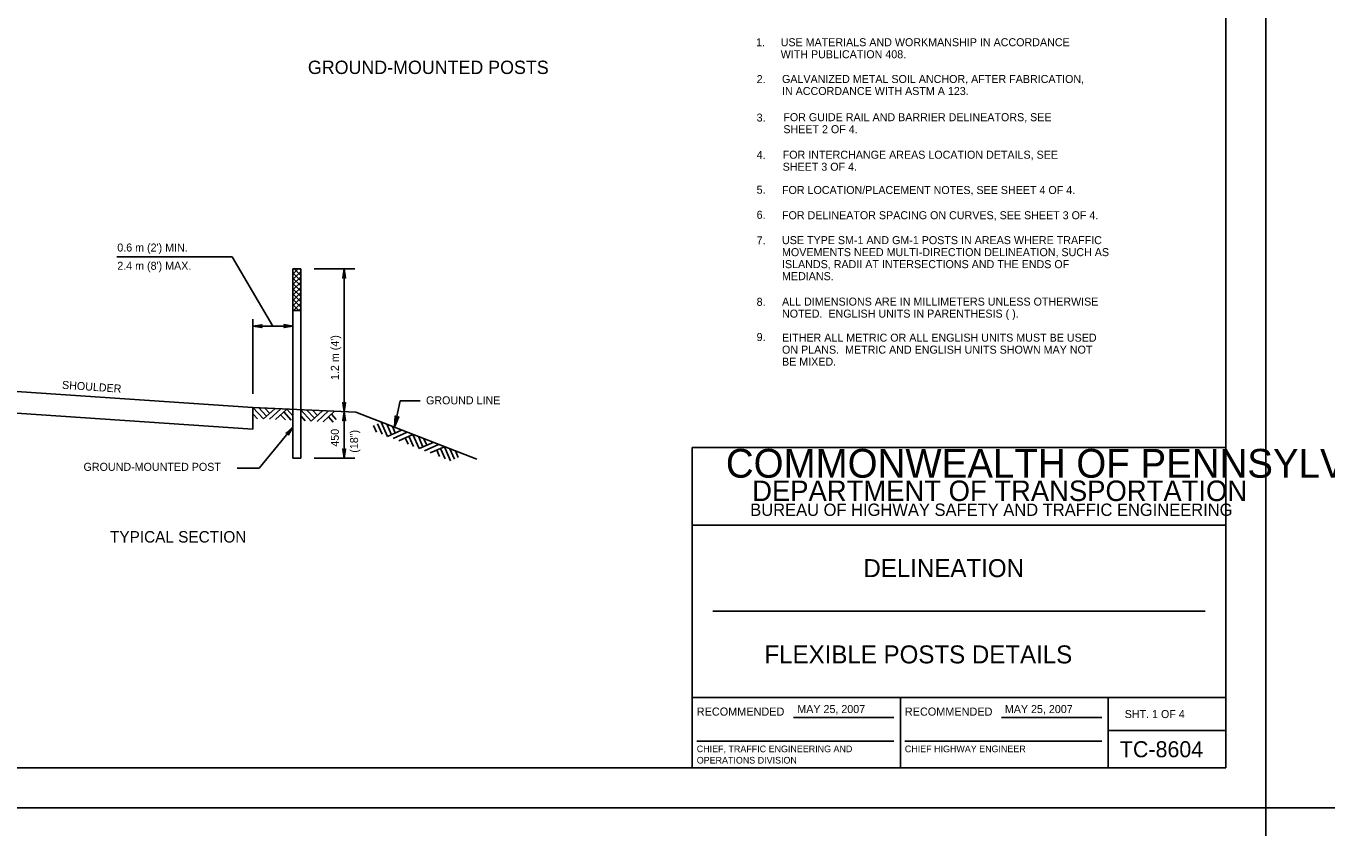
# Model space of a CAD drawing. Extents: x 640253 to 641999, y 298458 to 299646.
# Drawn here: x 640629.6 to 641116.9, y 299044.1 to 299344.6 of the extents above; entities that cross this region are included whole.
import ezdxf

# ---------------------------------------------------------------- set-up
doc = ezdxf.new("R2010")
doc.units = 0
for name, color, linetype in [('1', 7, 'Continuous'), ('2', 7, 'Continuous'), ('PLT-BNDY', 7, 'Continuous')]:
    doc.layers.add(name, color=color, linetype=linetype)

msp = doc.modelspace()

# ---------------------------------------------------------------- linework, layer by layer
at = {"layer": '1'}
for p, q in [((641079.31, 299066.63), (641079.31, 299630.63)), ((640879.31, 299066.63), (640879.31, 299186.63)), ((640879.31, 299186.63), (641079.31, 299186.63)), ((641079.31, 299157.63), (640879.31, 299157.63)), ((640887.06, 299125.31), (641071.56, 299125.31)), ((640879.31, 299093), (641079.31, 299093)), ((640957.31, 299093), (640957.31, 299066.63)), ((641035.19, 299066.63), (641035.19, 299093)), ((640917.24, 299085.57), (640954.87, 299085.57)), ((640995.24, 299085.57), (641032.87, 299085.57)), ((641035.19, 299080.63), (641079.31, 299080.63)), ((640880.99, 299076.68), (640954.87, 299076.68)), ((640958.99, 299076.68), (641032.87, 299076.68)), ((641079.31, 299066.63), (640293.31, 299066.63)), ((640293.31, 299066.63), (640879.31, 299066.63))]:
    msp.add_line(p, q, dxfattribs=at)
at = {"layer": '2'}
for p, q in [((640663.62, 299258.11), (640706.89, 299258.11)), ((640722.13, 299232.16), (640706.89, 299258.11)), ((640729.61, 299253.58), (640732.55, 299253.58)), ((640729.61, 299237.99), (640729.61, 299253.58)), ((640729.61, 299251.64), (640731.55, 299253.58)), ((640729.61, 299249.66), (640732.55, 299252.6)), ((640732.55, 299249.16), (640729.61, 299252.1)), ((640729.61, 299247.68), (640732.55, 299250.62)), ((640732.55, 299251.14), (640730.12, 299253.58)), ((640732.55, 299253.12), (640732.1, 299253.58)), ((640732.55, 299237.99), (640732.55, 299253.58)), ((640737.54, 299253.58), (640752.77, 299253.58)), ((640748.8, 299253.58), (640748.8, 299200.09)), ((640732.55, 299247.18), (640729.61, 299250.12)), ((640729.61, 299245.7), (640732.55, 299248.64)), ((640732.55, 299245.2), (640729.61, 299248.14)), ((640729.61, 299243.72), (640732.55, 299246.66)), ((640732.55, 299243.22), (640729.61, 299246.16)), ((640729.61, 299241.74), (640732.55, 299244.68)), ((640732.55, 299241.24), (640729.61, 299244.18)), ((640729.61, 299239.76), (640732.55, 299242.7)), ((640732.55, 299239.26), (640729.61, 299242.2)), ((640729.83, 299237.99), (640732.55, 299240.72)), ((640731.85, 299237.99), (640729.61, 299240.22)), ((640729.86, 299237.99), (640729.61, 299238.25)), ((640729.61, 299237.99), (640732.55, 299237.99)), ((640729.61, 299182.73), (640729.61, 299237.99)), ((640731.81, 299237.99), (640732.55, 299238.74)), ((640732.55, 299182.73), (640732.55, 299237.99)), ((640714.64, 299234.74), (640714.64, 299206.78)), ((640714.64, 299232.16), (640729.61, 299232.16)), ((640605.44, 299208.99), (640714.64, 299201.64)), ((640767.69, 299194.24), (640769.87, 299204.1)), ((640769.87, 299204.1), (640777.37, 299204.1)), ((640605.44, 299200.94), (640714.64, 299193.59)), ((640714.64, 299193.59), (640714.64, 299201.64)), ((640714.64, 299201.64), (640753.14, 299199.89)), ((640714.64, 299201.64), (640718.57, 299197.35)), ((640714.64, 299199.31), (640716.34, 299197.45)), ((640716.86, 299201.54), (640719.72, 299198.41)), ((640722.8, 299201.21), (640718.56, 299197.35)), ((640719.08, 299201.44), (640720.88, 299199.48)), ((640725.09, 299201.16), (640720.79, 299197.25)), ((640727.32, 299201.06), (640723.02, 299197.15)), ((640724.99, 299198.93), (640726.78, 299196.98)), ((640726.15, 299200), (640729.01, 299196.88)), ((640727.32, 299201.06), (640729.61, 299198.55)), ((640732.55, 299200.83), (640736.48, 299196.54)), ((640732.55, 299198.49), (640734.25, 299196.63)), ((640734.78, 299200.72), (640737.64, 299197.6)), ((640740.71, 299200.4), (640736.47, 299196.54)), ((640737, 299200.63), (640738.8, 299198.66)), ((640743, 299200.35), (640738.71, 299196.43)), ((640745.23, 299200.25), (640740.93, 299196.33)), ((640742.91, 299198.12), (640744.7, 299196.16)), ((640744.07, 299199.18), (640745.88, 299197.2)), ((640748.8, 299182.73), (640748.8, 299200.09)), ((640753.14, 299199.89), (640798.56, 299182.25)), ((640717.02, 299178.97), (640729.61, 299194.34)), ((640759.85, 299194.88), (640760.93, 299192.46)), ((640761.3, 299195.52), (640763.01, 299191.65)), ((640762.74, 299196.16), (640765.09, 299190.85)), ((640764.81, 299195.36), (640766.52, 299191.48)), ((640770.33, 299193.15), (640765.08, 299190.85)), ((640766.88, 299194.56), (640767.96, 299192.12)), ((640772.48, 299192.38), (640767.16, 299190.04)), ((640774.57, 299191.57), (640769.25, 299189.23)), ((640771.68, 299190.29), (640772.75, 299187.87)), ((640773.12, 299190.93), (640774.83, 299187.06)), ((640774.57, 299191.57), (640776.91, 299186.25)), ((640776.64, 299190.76), (640778.35, 299186.89)), ((640782.23, 299188.59), (640776.91, 299186.26)), ((640778.71, 299189.96), (640779.79, 299187.53)), ((640784.23, 299187.75), (640778.99, 299185.44)), ((640729.61, 299182.73), (640732.55, 299182.73)), ((640737.54, 299182.73), (640752.77, 299182.73)), ((640786.39, 299186.98), (640781.07, 299184.64)), ((640783.51, 299185.7), (640784.57, 299183.28)), ((640784.95, 299186.34), (640786.66, 299182.47)), ((640786.39, 299186.98), (640788.74, 299181.66)), ((640788.46, 299186.17), (640790.18, 299182.3)), ((640790.54, 299185.37), (640791.61, 299182.93)), ((640708.68, 299178.97), (640717.02, 299178.97))]:
    msp.add_line(p, q, dxfattribs=at)
for points in [[(640748.4, 299250.38), (640748.63, 299250.5), (640748.8, 299253.58), (640748.4, 299250.38), (640748.26, 299250.22), (640748.8, 299253.58), (640748.95, 299250.5), (640749.18, 299250.39), (640748.8, 299253.58), (640749.34, 299250.22), (640749.18, 299250.39)], [(640717.83, 299231.76), (640717.72, 299231.99), (640714.64, 299232.16), (640717.83, 299231.76), (640718, 299231.62), (640714.64, 299232.16), (640717.71, 299232.31), (640717.83, 299232.54), (640714.64, 299232.16), (640718, 299232.69), (640717.83, 299232.54)], [(640726.42, 299232.56), (640726.53, 299232.33), (640729.61, 299232.16), (640726.42, 299232.56), (640726.25, 299232.7), (640729.61, 299232.16), (640726.54, 299232.01), (640726.43, 299231.78), (640729.61, 299232.16), (640726.25, 299231.62), (640726.43, 299231.78)], [(640749.2, 299203.28), (640748.97, 299203.17), (640748.8, 299200.09), (640749.2, 299203.28), (640749.34, 299203.45), (640748.8, 299200.09), (640748.65, 299203.16), (640748.42, 299203.28), (640748.8, 299200.09), (640748.27, 299203.45), (640748.42, 299203.28)], [(640748.4, 299196.89), (640748.63, 299197.01), (640748.8, 299200.09), (640748.4, 299196.89), (640748.26, 299196.73), (640748.8, 299200.09), (640748.95, 299197.01), (640749.18, 299196.9), (640748.8, 299200.09), (640749.34, 299196.73), (640749.18, 299196.9)], [(640769.04, 299198.03), (640768.73, 299197.95), (640767.69, 299194.24), (640769.04, 299198.03), (640769.26, 299198.2), (640767.69, 299194.24), (640768.33, 299198.03), (640768.08, 299198.23), (640767.69, 299194.24), (640767.95, 299198.48), (640768.08, 299198.23)], [(640727.28, 299192.12), (640727.53, 299192.06), (640729.61, 299194.34), (640727.28, 299192.12), (640727.07, 299192.08), (640729.61, 299194.34), (640727.78, 299191.86), (640727.89, 299191.63), (640729.61, 299194.34), (640727.9, 299191.4), (640727.89, 299191.63)], [(640749.2, 299185.93), (640748.97, 299185.81), (640748.8, 299182.73), (640749.2, 299185.93), (640749.34, 299186.1), (640748.8, 299182.73), (640748.65, 299185.81), (640748.42, 299185.92), (640748.8, 299182.73), (640748.27, 299186.1), (640748.42, 299185.92)]]:
    msp.add_lwpolyline(points, dxfattribs=at)
at = {"layer": 'PLT-BNDY'}
for points in [[(640253.31, 299645.63), (641094.31, 299645.63), (641094.31, 299051.63), (640253.31, 299051.63)], [(641094.31, 299645.63), (641935.31, 299645.63), (641935.31, 299051.63), (641094.31, 299051.63)], [(640253.31, 299051.63), (641094.31, 299051.63), (641094.31, 298457.63), (640253.31, 298457.63)], [(641094.31, 299051.63), (641935.31, 299051.63), (641935.31, 298457.63), (641094.31, 298457.63)]]:
    msp.add_lwpolyline(points, close=True, dxfattribs=at)

# ---------------------------------------------------------------- texts
at = {"layer": '1'}
for s, height, p in [('COMMONWEALTH OF PENNSYLVANIA', 10.7828, (640891.9, 299175.36)), ('DEPARTMENT OF TRANSPORTATION', 7.6837, (640901.76, 299166.61)), ('BUREAU OF HIGHWAY SAFETY AND TRAFFIC ENGINEERING', 4.6253, (640901.04, 299161.04)), ('DELINEATION', 6.75, (640943.46, 299138.1)), ('FLEXIBLE POSTS DETAILS', 6.75, (640906.36, 299105.78)), ('RECOMMENDED', 3.048, (640880.99, 299086.2)), ('RECOMMENDED', 3.048, (640958.99, 299086.2)), ('SHT. 1 OF 4', 3, (641041.4, 299085.31)), ('CHIEF, TRAFFIC ENGINEERING AND', 2.5, (640880.99, 299072.51)), ('CHIEF HIGHWAY ENGINEER', 2.5, (640958.99, 299072.51)), ('TC-8604', 6, (641039.6, 299070.63)), ('OPERATIONS DIVISION', 2.5, (640880.99, 299068.26))]:
    msp.add_text(s, height=height, dxfattribs=at).set_placement(p)
at = {"layer": '2'}
for s, height, p in [('1.', 3, (640903.23, 299337)), ('USE MATERIALS AND WORKMANSHIP IN ACCORDANCE', 3, (640912.45, 299337)), ('WITH PUBLICATION 408.', 3, (640912.45, 299332.5)), ('GROUND-MOUNTED POSTS', 5, (640735.22, 299326.6)), ('2.', 3, (640903.43, 299323.18)), ('GALVANIZED METAL SOIL ANCHOR, AFTER FABRICATION,', 3, (640912.94, 299323.23)), ('IN ACCORDANCE WITH ASTM A 123.', 3, (640912.94, 299318.73)), ('3.', 3, (640903.43, 299308.78)), ('FOR GUIDE RAIL AND BARRIER DELINEATORS, SEE', 3, (640913.44, 299308.92)), ('SHEET 2 OF 4.', 3, (640913.44, 299304.42)), ('4.', 3, (640903.43, 299294.77)), ('FOR INTERCHANGE AREAS LOCATION DETAILS, SEE', 3, (640913.19, 299294.86)), ('SHEET 3 OF 4.', 3, (640913.19, 299290.36)), ('5.', 3, (640903.43, 299281.75)), ('FOR LOCATION/PLACEMENT NOTES, SEE SHEET 4 OF 4.', 3, (640912.94, 299281.64)), ('6.', 3, (640903.43, 299272.36)), ('FOR DELINEATOR SPACING ON CURVES, SEE SHEET 3 OF 4.', 3, (640912.94, 299272.19)), ('7.', 3, (640903.43, 299262.79)), ('USE TYPE SM-1 AND GM-1 POSTS IN AREAS WHERE TRAFFIC', 3, (640912.94, 299262.86)), ("0.6 m (2') MIN.", 3, (640663.78, 299260.09)), ('MOVEMENTS NEED MULTI-DIRECTION DELINEATION, SUCH AS', 3, (640912.94, 299258.36)), ("2.4 m (8') MAX.", 3, (640663.78, 299253.25)), ('ISLANDS, RADII AT INTERSECTIONS AND THE ENDS OF', 3, (640912.94, 299253.86)), ('MEDIANS.', 3, (640912.94, 299249.36)), ('8.', 3, (640903.43, 299239.75)), ('ALL DIMENSIONS ARE IN MILLIMETERS UNLESS OTHERWISE', 3, (640912.95, 299239.83)), ('NOTED.  ENGLISH UNITS IN PARENTHESIS ( ).', 3, (640912.95, 299235.33)), ('9.', 3, (640903.43, 299226.56)), ('EITHER ALL METRIC OR ALL ENGLISH UNITS MUST BE USED', 3, (640912.95, 299226.33)), ('ON PLANS.  METRIC AND ENGLISH UNITS SHOWN MAY NOT ', 3, (640912.95, 299221.83)), ('BE MIXED.', 3, (640912.95, 299217.33)), ('GROUND LINE', 3, (640779.51, 299202.84)), ('GROUND-MOUNTED POST', 3, (640651.13, 299177.93)), ('TYPICAL SECTION', 4.3, (640661.04, 299151.06)), ('MAY 25, 2007', 3, (640918.69, 299087.18)), ('MAY 25, 2007', 3, (640996.48, 299087.18))]:
    msp.add_text(s, height=height, dxfattribs=at).set_placement(p)
for s, rotation, p in [("1.2 m (4')", 90, (640746.83, 299211.95)), ('SHOULDER', 356.1494, (640642.99, 299208.68)), ('450', 90, (640746.83, 299186.97)), ('(18")', 90, (640754.03, 299184.71))]:
    msp.add_text(s, height=3, rotation=rotation, dxfattribs=at).set_placement(p)

doc.saveas('drawing.dxf')
